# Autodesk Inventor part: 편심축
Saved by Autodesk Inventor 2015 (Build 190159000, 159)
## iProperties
Created: 2025-08
Part Number: 편심축
Material: 일반
Document SubType Name: Modeling
Designer: user
Density: 1 g/cm^3
Appearance: 기본값
Author: user
Author: jhkim
Creation Date: 2025-08-05
Sending System: Autodesk Inventor 2026
Preprocessor: ST-DEVELOPER v20.1
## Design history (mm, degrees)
node "편심축1"
node "솔리드1"
node "기준1"
